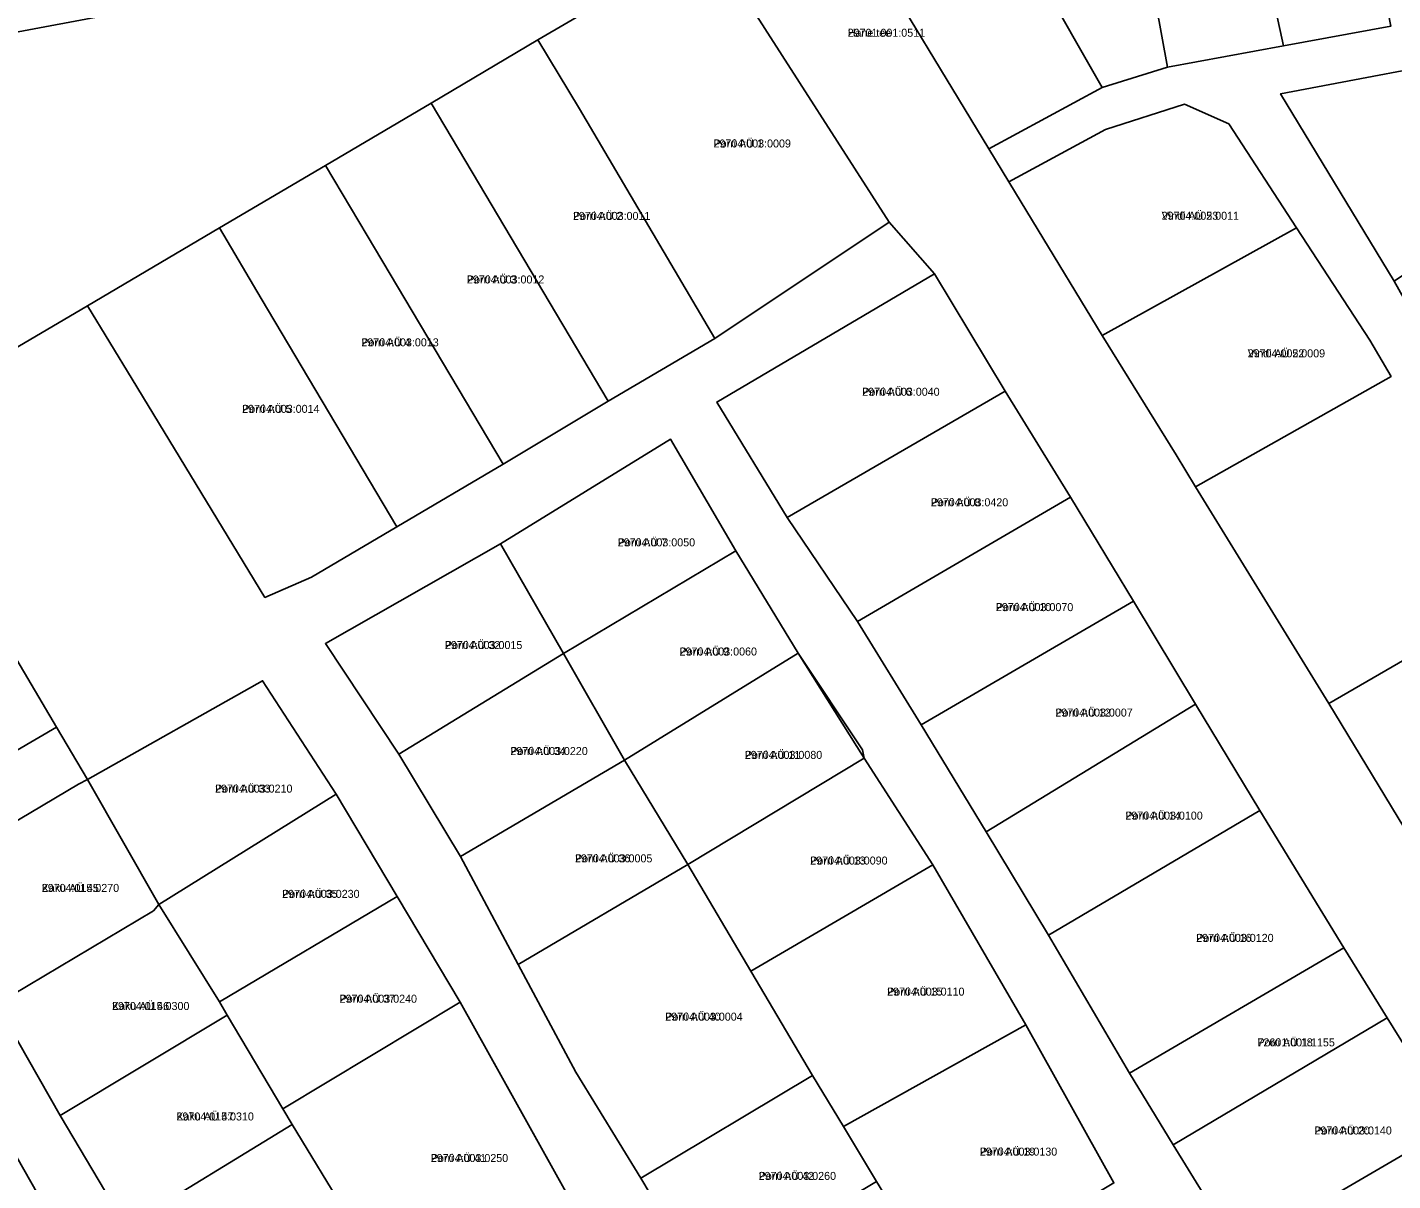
# Model space of a CAD drawing. Extents: x 504287 to 537970, y 6539941 to 6586214.
# Drawn here: x 516278.4 to 516534.2, y 6563721 to 6563937.1 of the extents above; entities that cross this region are included whole.
import ezdxf

# ---------------------------------------------------------------- set-up
doc = ezdxf.new("R2010")
doc.units = 0
for name, color, linetype in [('L_AADRESS', 7, 'Continuous'), ('PIIR', 7, 'Continuous'), ('TUNNUS', 7, 'Continuous')]:
    doc.layers.add(name, color=color, linetype=linetype)

msp = doc.modelspace()

# ---------------------------------------------------------------- linework, layer by layer
at = {"layer": 'PIIR'}
for points in [[(516504.01, 6563978.4), (516525.1, 6563982.59), (516533.9, 6563937.32), (516513.74, 6563933.61)], [(516483.78, 6563974.77), (516504.01, 6563978.4), (516513.74, 6563933.61), (516492, 6563929.64)], [(516464.05, 6563971.72), (516483.78, 6563974.77), (516492, 6563929.64), (516479.81, 6563925.81), (516456.18, 6563967.19)], [(516434.73, 6563953.6), (516456.18, 6563967.19), (516479.81, 6563925.81), (516458.55, 6563914.32)], [(516374, 6563934.73), (516404.7, 6563952.68), (516413.35, 6563941.9), (516439.89, 6563900.56), (516407.2, 6563878.8), (516381.83, 6563921.83)], [(516513.22, 6563924.64), (516534.48, 6563889.54), (516545.82, 6563869.35), (516566.07, 6563836.49), (516601.85, 6563859.06), (516637.63, 6563881.62), (516663.8, 6563898.32), (516664.83, 6563905.95), (516651.4, 6563927.39), (516636.37, 6563946.49), (516603.97, 6563941.74), (516576.02, 6563936.6), (516553.47, 6563932.24)], [(516354.03, 6563922.84), (516374, 6563934.73), (516381.83, 6563921.83), (516407.2, 6563878.8), (516387.24, 6563867.02), (516361.72, 6563909.91)], [(516553.47, 6563932.24), (516566.78, 6563911.27), (516534.48, 6563889.54), (516513.22, 6563924.64)], [(516334.24, 6563911.19), (516354.03, 6563922.84), (516361.72, 6563909.91), (516387.24, 6563867.02), (516367.51, 6563855.22), (516342.02, 6563898.1)], [(516462.27, 6563908.1), (516480.38, 6563917.91), (516495.21, 6563922.68), (516503.52, 6563918.98), (516516.23, 6563899.5), (516479.76, 6563879.35), (516466.75, 6563900.81)], [(516314.38, 6563899.5), (516334.24, 6563911.19), (516342.02, 6563898.1), (516367.51, 6563855.22), (516347.58, 6563843.49), (516322.21, 6563886.29)], [(516289.63, 6563884.92), (516314.38, 6563899.5), (516322.21, 6563886.29), (516347.58, 6563843.49), (516331.63, 6563834.05), (516322.89, 6563830.27), (516297.99, 6563871.18)], [(516479.76, 6563879.35), (516516.23, 6563899.5), (516529.94, 6563878.44), (516533.94, 6563871.65), (516497.3, 6563850.99), (516493.64, 6563856.96)], [(516407.56, 6563866.87), (516448.37, 6563890.87), (516461.6, 6563868.93), (516420.73, 6563845.22)], [(516461.6, 6563868.93), (516473.87, 6563849.02), (516433.95, 6563825.74), (516420.73, 6563845.22)], [(516398.87, 6563859.92), (516411.14, 6563839), (516378.86, 6563819.72), (516367.05, 6563840.31)], [(516433.95, 6563825.74), (516473.87, 6563849.02), (516485.66, 6563829.55), (516445.89, 6563806.35)], [(516233.36, 6563827.36), (516260.84, 6563844.83), (516283.8, 6563805.96), (516256.06, 6563789.77)], [(516348, 6563800.86), (516334.21, 6563821.6), (516367.05, 6563840.31), (516378.86, 6563819.72)], [(516378.86, 6563819.72), (516411.14, 6563839), (516422.83, 6563819.8), (516390.24, 6563799.73)], [(516522.28, 6563810.4), (516558.32, 6563831.23), (516572.5, 6563808.75), (516536.31, 6563787.22)], [(516485.66, 6563829.55), (516497.29, 6563810.28), (516458.03, 6563786.3), (516445.89, 6563806.35)], [(516348, 6563800.86), (516378.86, 6563819.72), (516390.24, 6563799.73), (516359.52, 6563781.72)], [(516390.24, 6563799.73), (516422.83, 6563819.8), (516435.19, 6563800.14), (516402.11, 6563780.2)], [(516289.62, 6563796.11), (516322.45, 6563814.65), (516336.23, 6563793.42), (516303.02, 6563772.71)], [(516458.03, 6563786.3), (516497.29, 6563810.28), (516509.33, 6563790.32), (516469.7, 6563766.95)], [(516359.52, 6563781.72), (516390.24, 6563799.73), (516402.11, 6563780.2), (516370.33, 6563761.49)], [(516402.11, 6563780.2), (516435.19, 6563800.14), (516448.07, 6563780.14), (516413.94, 6563760.25)], [(516258.77, 6563777.98), (516287.98, 6563795.25), (516289.62, 6563796.11), (516303.02, 6563772.71), (516302, 6563771.5), (516272.57, 6563754.02)], [(516303.02, 6563772.71), (516336.23, 6563793.42), (516347.65, 6563774.22), (516314.35, 6563754.5)], [(516469.7, 6563766.95), (516509.33, 6563790.32), (516525.09, 6563764.57), (516484.93, 6563741.11)], [(516370.33, 6563761.49), (516402.11, 6563780.2), (516413.94, 6563760.25), (516425.5, 6563740.68), (516393.32, 6563721.41), (516381.14, 6563741.27)], [(516425.5, 6563740.68), (516413.94, 6563760.25), (516448.07, 6563780.14), (516465.46, 6563750.19), (516431.29, 6563731.14)], [(516272.57, 6563754.02), (516302, 6563771.5), (516303.02, 6563772.71), (516314.35, 6563754.5), (516315.84, 6563751.99), (516284.51, 6563733.19)], [(516315.84, 6563751.99), (516314.35, 6563754.5), (516347.65, 6563774.22), (516359.48, 6563754.42), (516326.26, 6563734.4)], [(516533.21, 6563751.45), (516493.11, 6563727.7), (516484.93, 6563741.11), (516525.09, 6563764.57)], [(516340.78, 6563710.41), (516338.17, 6563714.73), (516328.01, 6563731.51), (516326.26, 6563734.4), (516359.48, 6563754.42), (516381.69, 6563714.5), (516349.89, 6563695.37)], [(516295.37, 6563714.86), (516284.51, 6563733.19), (516315.84, 6563751.99), (516326.26, 6563734.4), (516328.01, 6563731.51), (516296.93, 6563712.51)], [(516437.49, 6563720.84), (516431.29, 6563731.14), (516465.46, 6563750.19), (516481.98, 6563720.54), (516449.55, 6563701.12)], [(516493.11, 6563727.7), (516533.21, 6563751.45), (516545.71, 6563731.34), (516505.34, 6563707.79)], [(516393.32, 6563721.41), (516425.5, 6563740.68), (516431.29, 6563731.14), (516437.49, 6563720.84), (516405.19, 6563701.54)], [(516298.27, 6563709.76), (516296.93, 6563712.51), (516328.01, 6563731.51), (516338.17, 6563714.73), (516340.78, 6563710.41), (516309.14, 6563691.96)], [(516505.34, 6563707.79), (516545.71, 6563731.34), (516556.93, 6563712.69), (516517.08, 6563688.04)], [(516245.73, 6563710.1), (516275.07, 6563727.69), (516287.14, 6563706.42), (516259.16, 6563689.81)]]:
    msp.add_lwpolyline(points, close=True, dxfattribs=at)
for points in [[(516382.23, 6563956.06), (516107.14, 6563904.56)], [(516107.14, 6563904.56), (516382.23, 6563956.06)], [(516404.7, 6563952.68), (516374, 6563934.73), (516354.03, 6563922.84), (516334.24, 6563911.19), (516314.38, 6563899.5), (516289.63, 6563884.92), (516250.7, 6563862)], [(516434.73, 6563953.6), (516458.55, 6563914.32), (516462.27, 6563908.1), (516466.75, 6563900.81), (516479.76, 6563879.35), (516493.64, 6563856.96), (516497.3, 6563850.99), (516522.28, 6563810.4), (516536.31, 6563787.22)], [(516545.71, 6563731.34), (516533.21, 6563751.45), (516525.09, 6563764.57), (516509.33, 6563790.32), (516497.29, 6563810.28), (516485.66, 6563829.55), (516473.87, 6563849.02), (516461.6, 6563868.93), (516448.37, 6563890.87), (516439.89, 6563900.56), (516413.35, 6563941.9)], [(516558.32, 6563831.23), (516522.28, 6563810.4), (516497.3, 6563850.99), (516533.94, 6563871.65), (516529.94, 6563878.44), (516516.23, 6563899.5), (516503.52, 6563918.98), (516495.21, 6563922.68), (516480.38, 6563917.91), (516462.27, 6563908.1), (516458.55, 6563914.32), (516479.81, 6563925.81), (516492, 6563929.64), (516513.74, 6563933.61), (516533.9, 6563937.32)], [(516250.7, 6563862), (516289.63, 6563884.92), (516297.99, 6563871.18), (516322.89, 6563830.27), (516331.63, 6563834.05), (516347.58, 6563843.49), (516367.51, 6563855.22), (516387.24, 6563867.02), (516407.2, 6563878.8), (516439.89, 6563900.56), (516448.37, 6563890.87), (516407.56, 6563866.87), (516420.73, 6563845.22), (516433.95, 6563825.74), (516445.89, 6563806.35), (516458.03, 6563786.3), (516469.7, 6563766.95), (516484.93, 6563741.11), (516493.11, 6563727.7), (516505.34, 6563707.79), (516517.08, 6563688.04), (516528.99, 6563668.1), (516540.37, 6563648.81)], [(516481.98, 6563720.54), (516465.46, 6563750.19), (516448.07, 6563780.14), (516435.19, 6563800.14), (516434.89, 6563801.71), (516422.83, 6563819.8), (516411.14, 6563839), (516398.87, 6563859.92), (516367.05, 6563840.31), (516334.21, 6563821.6), (516348, 6563800.86), (516359.52, 6563781.72), (516370.33, 6563761.49), (516381.14, 6563741.27), (516393.32, 6563721.41), (516405.19, 6563701.54)], [(516381.69, 6563714.5), (516370.46, 6563734.68), (516359.48, 6563754.42), (516347.65, 6563774.22), (516336.23, 6563793.42), (516322.45, 6563814.65), (516289.62, 6563796.11), (516283.8, 6563805.96), (516260.84, 6563844.83)], [(516256.06, 6563789.77), (516283.8, 6563805.96), (516289.62, 6563796.11), (516287.98, 6563795.25), (516258.77, 6563777.98)], [(516272.57, 6563754.02), (516284.51, 6563733.19), (516295.37, 6563714.86)], [(516287.14, 6563706.42), (516275.07, 6563727.69)]]:
    msp.add_lwpolyline(points, dxfattribs=at)

# ---------------------------------------------------------------- texts
at = {"layer": 'L_AADRESS'}
for s, p in [('Hane tee', (516432.1, 6563935.31)), ('Porri AÜ 1', (516406.95, 6563914.56)), ('Porri AÜ 2', (516380.62, 6563900.99)), ('Vindi AÜ 23', (516490.93, 6563901.02)), ('Porri AÜ 3', (516360.74, 6563889.08)), ('Porri AÜ 4', (516340.95, 6563877.3)), ('Vindi AÜ 22', (516507.06, 6563875.24)), ('Porri AÜ 6', (516434.82, 6563868.04)), ('Porri AÜ 5', (516318.61, 6563864.84)), ('Porri AÜ 8', (516447.68, 6563847.33)), ('Porri AÜ 7', (516389, 6563839.82)), ('Porri AÜ 10', (516459.87, 6563827.69)), ('Porri AÜ 32', (516356.62, 6563820.58)), ('Porri AÜ 9', (516400.59, 6563819.37)), ('Porri AÜ 12', (516471.01, 6563807.93)), ('Porri AÜ 34', (516368.88, 6563800.72)), ('Porri AÜ 11', (516412.82, 6563800)), ('Porri AÜ 33', (516313.54, 6563793.68)), ('Porri AÜ 14', (516484.13, 6563788.62)), ('Porri AÜ 36', (516380.99, 6563780.61)), ('Porri AÜ 13', (516425.07, 6563780.2)), ('Kaku AÜ 45', (516281.06, 6563775.07)), ('Porri AÜ 35', (516326.12, 6563773.96)), ('Porri AÜ 16', (516497.41, 6563765.71)), ('Porri AÜ 15', (516439.48, 6563755.64)), ('Kaku AÜ 46', (516294.23, 6563752.95)), ('Porri AÜ 37', (516336.88, 6563754.31)), ('Porri AÜ 40', (516397.91, 6563750.95)), ('Porri AÜ 18', (516508.88, 6563746.13)), ('Kaku AÜ 47', (516306.31, 6563732.25)), ('Porri AÜ 20', (516519.56, 6563729.62)), ('Porri AÜ 41', (516353.97, 6563724.46)), ('Porri AÜ 19', (516456.86, 6563725.66)), ('Porri AÜ 42', (516415.41, 6563721.11))]:
    msp.add_text(s, height=1.5, dxfattribs=at).set_placement(p)
at = {"layer": 'TUNNUS'}
for s, p in [('29701:001:0511', (516432.1, 6563935.31)), ('29704:003:0009', (516406.95, 6563914.56)), ('29704:003:0011', (516380.62, 6563900.99)), ('29704:005:0011', (516490.93, 6563901.02)), ('29704:003:0012', (516360.74, 6563889.08)), ('29704:003:0013', (516340.95, 6563877.3)), ('29704:005:0009', (516507.06, 6563875.24)), ('29704:003:0040', (516434.82, 6563868.04)), ('29704:003:0014', (516318.61, 6563864.84)), ('29704:003:0420', (516447.68, 6563847.33)), ('29704:003:0050', (516389, 6563839.82)), ('29704:003:0070', (516459.87, 6563827.69)), ('29704:003:0015', (516356.62, 6563820.58)), ('29704:003:0060', (516400.59, 6563819.37)), ('29704:003:0007', (516471.01, 6563807.93)), ('29704:003:0220', (516368.88, 6563800.72)), ('29704:003:0080', (516412.82, 6563800)), ('29704:003:0210', (516313.54, 6563793.68)), ('29704:003:0100', (516484.13, 6563788.62)), ('29704:003:0005', (516380.99, 6563780.61)), ('29704:003:0090', (516425.07, 6563780.2)), ('29704:015:0270', (516281.06, 6563775.07)), ('29704:003:0230', (516326.12, 6563773.96)), ('29704:003:0120', (516497.41, 6563765.71)), ('29704:003:0110', (516439.48, 6563755.64)), ('29704:015:0300', (516294.23, 6563752.95)), ('29704:003:0240', (516336.88, 6563754.31)), ('29704:003:0004', (516397.91, 6563750.95)), ('72601:001:1155', (516508.88, 6563746.13)), ('29704:015:0310', (516306.31, 6563732.25)), ('29704:003:0140', (516519.56, 6563729.62)), ('29704:003:0130', (516456.86, 6563725.66)), ('29704:003:0250', (516353.97, 6563724.46)), ('29704:003:0260', (516415.41, 6563721.11))]:
    msp.add_text(s, height=1.5, dxfattribs=at).set_placement(p)

doc.saveas('drawing.dxf')
